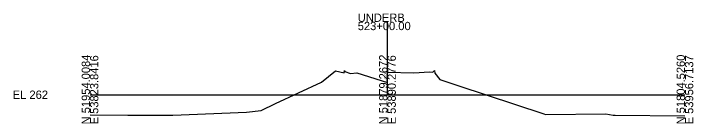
# Model space of a CAD drawing. Extents: x 12366 to 12594, y 96215 to 101752.
# Drawn here: x 12365.6 to 12594.1, y 101714.9 to 101752 of the extents above; entities that cross this region are included whole.
import ezdxf

# ---------------------------------------------------------------- set-up
doc = ezdxf.new("R2010")
doc.units = 0
for name, color, linetype in [('Level 10', 7, 'Continuous'), ('Level 60', 7, 'Continuous'), ('Level 63', 7, 'Continuous')]:
    doc.layers.add(name, color=color, linetype=linetype)

msp = doc.modelspace()

# ---------------------------------------------------------------- linework, layer by layer
at = {"layer": 'Level 60'}
for p, q in [((12469.15, 101728.88), (12473.84, 101732.74)), ((12473.84, 101732.74), (12476.71, 101732.06)), ((12476.71, 101732.06), (12476.83, 101732.79)), ((12476.83, 101732.79), (12476.92, 101732.53)), ((12476.92, 101732.53), (12478.86, 101731.75)), ((12478.86, 101731.75), (12481.05, 101732.02)), ((12481.05, 101732.02), (12491.3, 101728.72)), ((12491.3, 101728.72), (12491.31, 101732.27)), ((12491.31, 101732.27), (12500.14, 101732.07)), ((12500.14, 101732.07), (12505.42, 101732.32)), ((12505.42, 101732.32), (12506.56, 101732.26)), ((12506.56, 101732.26), (12507.14, 101732.83)), ((12507.14, 101732.83), (12507.27, 101731.9)), ((12507.27, 101731.9), (12508.86, 101729.79)), ((12453.69, 101721.63), (12469.15, 101728.88)), ((12508.86, 101729.79), (12514.95, 101727.71)), ((12514.95, 101727.71), (12543.85, 101718.22)), ((12448.89, 101719.37), (12453.69, 101721.63)), ((12443.95, 101718.78), (12448.89, 101719.37)), ((12391.3, 101717.83), (12404.01, 101717.7)), ((12404.01, 101717.7), (12418.63, 101717.69)), ((12418.63, 101717.69), (12419.18, 101717.69)), ((12419.18, 101717.69), (12443.95, 101718.78)), ((12543.85, 101718.22), (12544.47, 101718)), ((12544.47, 101718), (12564.76, 101718.21)), ((12564.76, 101718.21), (12567.15, 101717.71)), ((12567.15, 101717.71), (12567.8, 101717.71)), ((12567.8, 101717.71), (12591.3, 101717.55))]:
    msp.add_line(p, q, dxfattribs=at)
at = {"layer": 'Level 63'}
for p, q in [((12491.3, 101724.64), (12491.3, 101749.23)), ((12391.3, 101724.64), (12491.3, 101724.64)), ((12491.3, 101724.64), (12591.3, 101724.64))]:
    msp.add_line(p, q, dxfattribs=at)

# ---------------------------------------------------------------- texts
at = {"layer": 'Level 10'}
msp.add_text('266.08', height=0.6, rotation=90, dxfattribs=at).set_placement((12490.9, 101729.72))
at = {"layer": 'Level 63'}
for s, p in [('UNDERB', (12481.3, 101749.23)), ('523+00.00', (12481.3, 101746.43)), ('EL 262', (12365.31, 101723.24))]:
    msp.add_text(s, height=2.8, dxfattribs=at).set_placement(p)
for s, p in [('N 51954.0084', (12391.3, 101714.64)), ('E 53823.8416', (12394.1, 101714.64)), ('N 51879.2672', (12491.3, 101714.64)), ('E 53890.2776', (12494.1, 101714.64)), ('N 51804.5260', (12591.3, 101714.64)), ('E 53956.7137', (12594.1, 101714.64))]:
    msp.add_text(s, height=2.8, rotation=90, dxfattribs=at).set_placement(p)

doc.saveas('drawing.dxf')
